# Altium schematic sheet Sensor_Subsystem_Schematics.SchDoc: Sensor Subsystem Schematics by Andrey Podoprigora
size A4; SheetNumber: 1; SheetTotal: 1
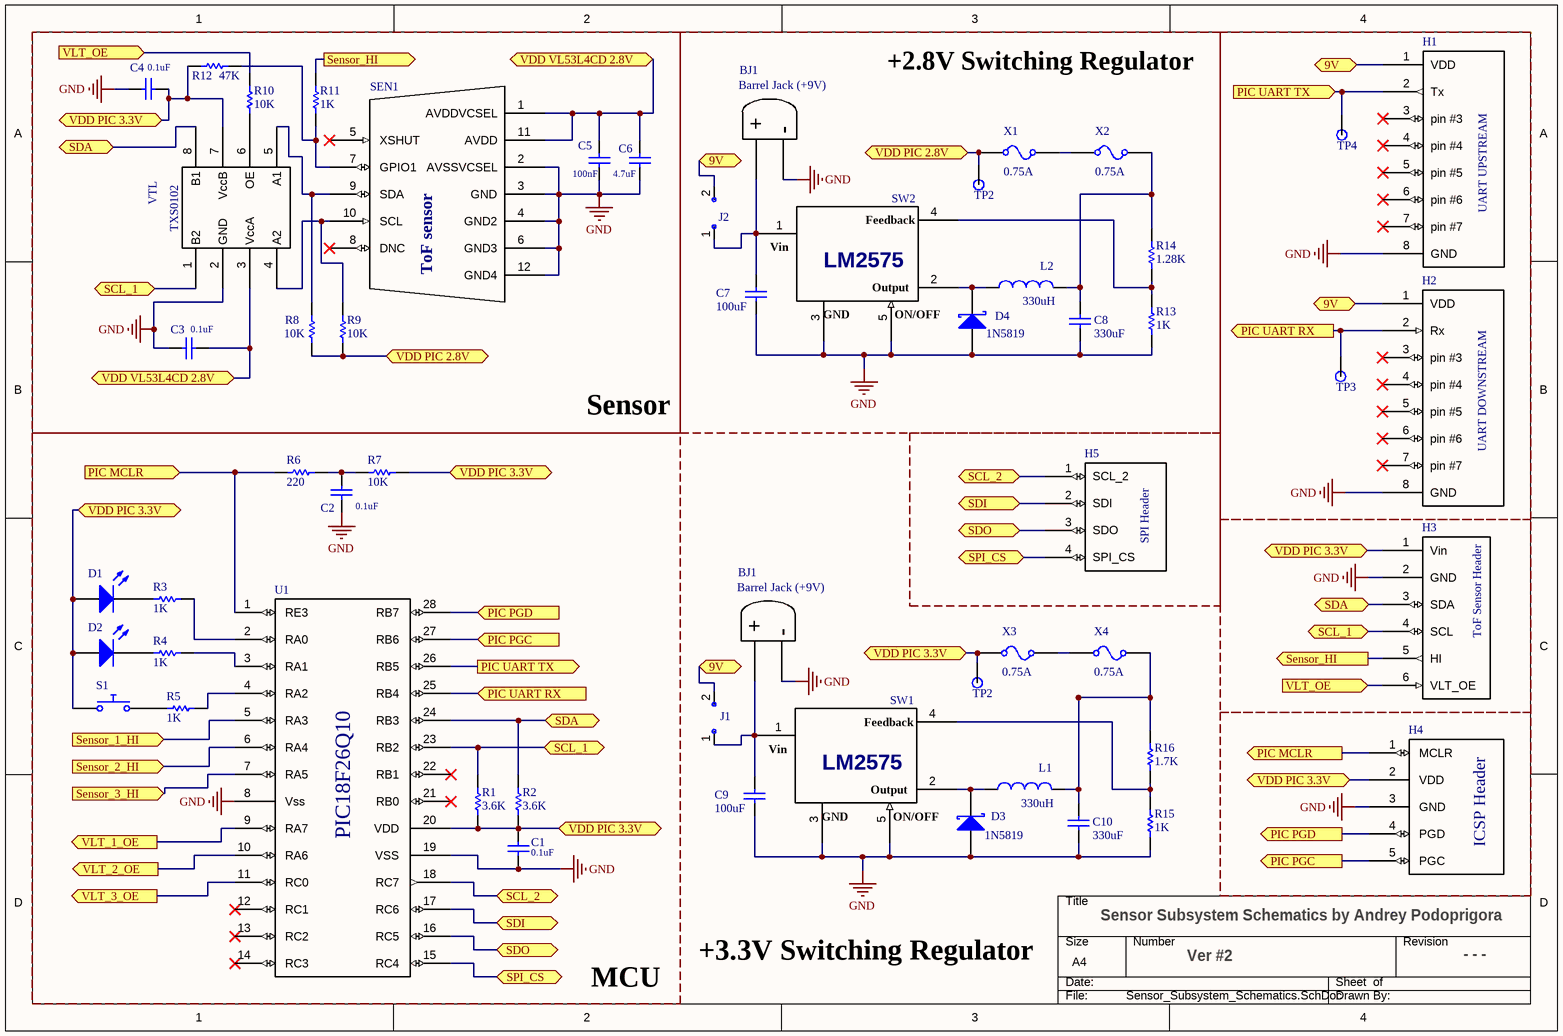
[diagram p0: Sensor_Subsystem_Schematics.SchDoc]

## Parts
(Parts that share a designator on the sheet are numbered #1, #2 ... from top to bottom, then left to right.)
BJ1#1  AP_Barrel_Jack_9v  (value not drawn)
BJ1#2  AP_Barrel_Jack_9v  (value not drawn)
C1  value 0.1uF  (hidden comment: Capacitor)
C2  value 0.1uF  (hidden comment: Capacitor)
C3  value 0.1uF  (hidden comment: Capacitor)
C4  value 0.1uF  (hidden comment: Capacitor)
C5  value 100nF  (hidden comment: Capacitor)
C6  value 4.7uF  (hidden comment: Capacitor)
C7  value 100uF  (hidden comment: Capacitor)
C8  value 330uF  (hidden comment: Capacitor)
C9  value 100uF  (hidden comment: Capacitor)
C10  value 330uF  (hidden comment: Capacitor)
D1  Light-Emitting Diode  (value not drawn)
D2  Light-Emitting Diode  (value not drawn)
D3  1N5819
D4  1N5819
H1  AP_UART_US  (value not drawn)
H2  AP_UART_DS  (value not drawn)
H3  AP_ToF_Header  (value not drawn)
H4  AP_ICSP_Header  (value not drawn)
H5  AP_SPI_Header  (value not drawn)
J1  AP_Jumper  (value not drawn)
J2  AP_Jumper  (value not drawn)
L1  value 330uH  (hidden comment: Inductor)
L2  value 330uH  (hidden comment: Inductor)
R1  value 3.6K  (hidden comment: Resistor)
R2  value 3.6K  (hidden comment: Resistor)
R3  value 1K  (hidden comment: Resistor)
R4  value 1K  (hidden comment: Resistor)
R5  value 1K  (hidden comment: Resistor)
R6  value 220  (hidden comment: Resistor)
R7  value 10K  (hidden comment: Resistor)
R8  value 10K  (hidden comment: Resistor)
R9  value 10K  (hidden comment: Resistor)
R10  value 10K  (hidden comment: Resistor)
R11  value 1K  (hidden comment: Resistor)
R12  value 47K  (hidden comment: Resistor)
R13  value 1K  (hidden comment: Resistor)
R14  value 1.28K  (hidden comment: Resistor)
R15  value 1K  (hidden comment: Resistor)
R16  value 1.7K  (hidden comment: Resistor)
S1  Push Button Normally Opened  (value not drawn)
SEN1  AP_VL53L4CD  (value not drawn)
SW1  AP_LM2575  (value not drawn)
SW2  AP_LM2575  (value not drawn)
TP2#1  AP_TP  (value not drawn)
TP2#2  AP_TP  (value not drawn)
TP3  AP_TP  (value not drawn)
TP4  AP_TP  (value not drawn)
U1  AP_PIC18F26Q10  (value not drawn)
VTL  AP_TXS0102  (value not drawn)
X1  CURRENT: 0.75A  (hidden comment: Fuse)
X2  CURRENT: 0.75A  (hidden comment: Fuse)
X3  CURRENT: 0.75A  (hidden comment: Fuse)
X4  CURRENT: 0.75A  (hidden comment: Fuse)

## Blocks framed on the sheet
Sensor: C3-C6 R8-R12 SEN1 VTL
+2.8V Switching Regulator: BJ1#1 C7 C8 D4 J2 L2 R13 R14 SW2 TP2#1 X1 X2
MCU: C1 C2 D1 D2 R1-R7 S1 U1

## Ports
9V (bidir, see Sensor_Subsystem_Schematics[1C], Sensor_Subsystem_Schematics[1D], Sensor_Subsystem_Schematics[3B]), 9V (bidir, see Sensor_Subsystem_Schematics[1C], Sensor_Subsystem_Schematics[1D], Sensor_Subsystem_Schematics[3D]), 9V (bidir, see Sensor_Subsystem_Schematics[1C], Sensor_Subsystem_Schematics[3B], Sensor_Subsystem_Schematics[3D]), 9V (bidir, see Sensor_Subsystem_Schematics[1D], Sensor_Subsystem_Schematics[3B], Sensor_Subsystem_Schematics[3D]), PIC MCLR (in, see Sensor_Subsystem_Schematics[1B]), PIC MCLR (out, see Sensor_Subsystem_Schematics[4C]), PIC PGC (in, see Sensor_Subsystem_Schematics[1A]), PIC PGC (out, see Sensor_Subsystem_Schematics[3B]), PIC PGD (in, see Sensor_Subsystem_Schematics[1A]), PIC PGD (out, see Sensor_Subsystem_Schematics[3B]), PIC UART RX (in, see Sensor_Subsystem_Schematics[1C]), PIC UART RX (out, see Sensor_Subsystem_Schematics[3B]), PIC UART TX (in, see Sensor_Subsystem_Schematics[3B]), PIC UART TX (out, see Sensor_Subsystem_Schematics[1D]), SCL_1 (bidir, see Sensor_Subsystem_Schematics[1B], Sensor_Subsystem_Schematics[3B]), SCL_1 (bidir, see Sensor_Subsystem_Schematics[1B], Sensor_Subsystem_Schematics[4C]), SCL_1 (bidir, see Sensor_Subsystem_Schematics[3B], Sensor_Subsystem_Schematics[4C]), SCL_2 (bidir, see Sensor_Subsystem_Schematics[2C]), SCL_2 (bidir, see Sensor_Subsystem_Schematics[3A]), SDA (bidir, see Sensor_Subsystem_Schematics[1B], Sensor_Subsystem_Schematics[3B]), SDA (bidir, see Sensor_Subsystem_Schematics[1B], Sensor_Subsystem_Schematics[4D]), SDA (bidir, see Sensor_Subsystem_Schematics[3B], Sensor_Subsystem_Schematics[4D]), SDI (bidir, see Sensor_Subsystem_Schematics[2C]), SDI (bidir, see Sensor_Subsystem_Schematics[3A]), SDO (bidir, see Sensor_Subsystem_Schematics[2B]), SDO (bidir, see Sensor_Subsystem_Schematics[3A]), Sensor_1_HI (in), Sensor_2_HI (in), Sensor_3_HI (in), Sensor_HI (out, see Sensor_Subsystem_Schematics[1B]), Sensor_HI (out, see Sensor_Subsystem_Schematics[4D]), SPI_CS (bidir, see Sensor_Subsystem_Schematics[2B]), SPI_CS (bidir, see Sensor_Subsystem_Schematics[3A]), VDD PIC 2.8V (bidir, see Sensor_Subsystem_Schematics[2D]), VDD PIC 2.8V (bidir, see Sensor_Subsystem_Schematics[4C]), VDD PIC 3.3V (bidir, see Sensor_Subsystem_Schematics[1A], Sensor_Subsystem_Schematics[1B], Sensor_Subsystem_Schematics[2B], Sensor_Subsystem_Schematics[3A], Sensor_Subsystem_Schematics[3C], Sensor_Subsystem_Schematics[4C]), VDD PIC 3.3V (bidir, see Sensor_Subsystem_Schematics[1A], Sensor_Subsystem_Schematics[1B], Sensor_Subsystem_Schematics[2B], Sensor_Subsystem_Schematics[3A], Sensor_Subsystem_Schematics[3C], Sensor_Subsystem_Schematics[4D]), VDD PIC 3.3V (bidir, see Sensor_Subsystem_Schematics[1A], Sensor_Subsystem_Schematics[1B], Sensor_Subsystem_Schematics[2B], Sensor_Subsystem_Schematics[3A], Sensor_Subsystem_Schematics[4C], Sensor_Subsystem_Schematics[4D]), VDD PIC 3.3V (bidir, see Sensor_Subsystem_Schematics[1A], Sensor_Subsystem_Schematics[1B], Sensor_Subsystem_Schematics[2B], Sensor_Subsystem_Schematics[3C], Sensor_Subsystem_Schematics[4C], Sensor_Subsystem_Schematics[4D]), VDD PIC 3.3V (bidir, see Sensor_Subsystem_Schematics[1A], Sensor_Subsystem_Schematics[1B], Sensor_Subsystem_Schematics[3A], Sensor_Subsystem_Schematics[3C], Sensor_Subsystem_Schematics[4C], Sensor_Subsystem_Schematics[4D]), VDD PIC 3.3V (bidir, see Sensor_Subsystem_Schematics[1A], Sensor_Subsystem_Schematics[2B], Sensor_Subsystem_Schematics[3A], Sensor_Subsystem_Schematics[3C], Sensor_Subsystem_Schematics[4C], Sensor_Subsystem_Schematics[4D]), VDD PIC 3.3V (bidir, see Sensor_Subsystem_Schematics[1B], Sensor_Subsystem_Schematics[2B], Sensor_Subsystem_Schematics[3A], Sensor_Subsystem_Schematics[3C], Sensor_Subsystem_Schematics[4C], Sensor_Subsystem_Schematics[4D]), VDD VL53L4CD 2.8V (bidir, see Sensor_Subsystem_Schematics[3D]), VDD VL53L4CD 2.8V (bidir, see Sensor_Subsystem_Schematics[4C]), VLT_1_OE (out), VLT_2_OE (out), VLT_3_OE (out), VLT_OE (in, see Sensor_Subsystem_Schematics[1B]), VLT_OE (in, see Sensor_Subsystem_Schematics[4D])

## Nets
GND: BJ1#1.1(-) BJ1#2.1(-) C1.1 C2.1 C3.1 C4.1 C5.1 C6.1 C7.1 C8.1 C9.1 C10.1 D3.1(A) D4.1(A) H1.8(GND) H2.8(GND) H3.2(GND) H4.3(GND) R13.1 R15.1 SEN1.2(AVSSVCSEL) SEN1.3(GND) SEN1.4(GND2) SEN1.6(GND3) SEN1.12(GND4) SW1.3(GND) SW1.5(ON/OFF) SW2.3(GND) SW2.5(ON/OFF) U1.8(Vss) U1.19(VSS) VTL.2(GND)
9V: H1.1(VDD) H2.1(VDD) J1.2 J2.2 ; port 9V
PIC MCLR: H4.1(MCLR) R6.1 U1.1(RE3) ; port PIC MCLR
PIC PGC: H4.5(PGC) U1.27(RB6) ; port PIC PGC
PIC PGD: H4.4(PGD) U1.28(RB7) ; port PIC PGD
PIC UART RX: H2.2(Rx) TP3.31 U1.25(RB4) ; port PIC UART RX
PIC UART TX: H1.2(Tx) TP4.31 U1.26(RB5) ; port PIC UART TX
SCL_1: H3.4(SCL) R1.2 U1.23(RB2) VTL.1(B2) ; port SCL_1
SCL_2: H5.1(SCL_2) U1.18(RC7) ; port SCL_2
SDA: H3.3(SDA) R2.2 U1.24(RB3) VTL.8(B1) ; port SDA
SDI: H5.2(SDI) U1.17(RC6) ; port SDI
SDO: H5.3(SDO) U1.16(RC5) ; port SDO
Sensor_1_HI: U1.5(RA3) ; port Sensor_1_HI
Sensor_2_HI: U1.6(RA4) ; port Sensor_2_HI
Sensor_3_HI: U1.7(RA5) ; port Sensor_3_HI
Sensor_HI: H3.5(HI) R11.2 ; port Sensor_HI
SPI_CS: H5.4(SPI_CS) U1.15(RC4) ; port SPI_CS
VDD PIC 2.8V: R8.1 R9.1 TP2#1.31 X1.1 ; port VDD PIC 2.8V
VDD PIC 3.3V: C1.2 C4.2 D1.1(A) D2.1(A) H3.1(Vin) H4.2(VDD) R1.1 R2.1 R7.2 R12.1 S1.1 TP2#2.31 U1.20(VDD) VTL.7(VccB) X3.1 ; port VDD PIC 3.3V
VDD VL53L4CD 2.8V: C3.2 C5.2 C6.2 SEN1.1(AVDDVCSEL) SEN1.11(AVDD) VTL.3(VccA) ; port VDD VL53L4CD 2.8V
VLT_1_OE: U1.9(RA7) ; port VLT_1_OE
VLT_2_OE: U1.10(RA6) ; port VLT_2_OE
VLT_3_OE: U1.11(RC0) ; port VLT_3_OE
VLT_OE: H3.6(VLT_OE) R10.2 ; port VLT_OE
NetBJ1#1_1: BJ1#1.1(+) C7.2 J2.1 SW2.1(Vin)
NetBJ1#2_1: BJ1#2.1(+) C9.2 J1.1 SW1.1(Vin)
NetC2_2: C2.2 R6.2 R7.1
NetC8_2: C8.2 L2.2 R14.2 X2.2
NetC10_2: C10.2 L1.2 R16.2 X4.2
NetD1_2: D1.2(K) R3.1
NetD2_2: D2.2(K) R4.1
NetD3_2: D3.2(K) L1.1 SW1.2(Output)
NetD4_2: D4.2(K) L2.1 SW2.2(Output)
NetR3_2: R3.2 U1.2(RA0)
NetR4_2: R4.2 U1.3(RA1)
NetR5_1: R5.1 S1.2
NetR5_2: R5.2 U1.4(RA2)
NetR8_2: R8.2 SEN1.9(SDA) VTL.5(A1)
NetR9_2: R9.2 SEN1.10(SCL) VTL.4(A2)
NetR10_1: R10.1 VTL.6(OE)
NetR11_1: R11.1 R12.2 SEN1.7(GPIO1)
NetR13_2: R13.2 R14.1 SW2.4(Feedback)
NetR15_2: R15.2 R16.1 SW1.4(Feedback)
NetX1_2: X1.2 X2.1
NetX3_2: X3.2 X4.1

Not connected (* = marked no-connect by the designer): H1 3(pin_#3)* 4(pin_#4)* 5(pin_#5)* 6(pin_#6)* 7(pin_#7)*; H2 3(pin_#3)* 4(pin_#4)* 5(pin_#5)* 6(pin_#6)* 7(pin_#7)*; SEN1 5(XSHUT)* 8(DNC)*; U1 12(RC1)* 13(RC2)* 14(RC3)* 21(RB0)* 22(RB1)*

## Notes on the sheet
- +3.3V Switching Regulator
- Ver #2
- - - -

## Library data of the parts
C1-C10 = Capacitor: SimulationGenericComponent: True
D1 D2 = LED: AF: 1; BV: 0; BV_MAX: 1e99; EG: 1.11; FC: 0.5; IBV: 0.001; IS: 1e-14; MJSW: 0.33; NTUN: 30; TNOM: 27; XTI: 3; SimulationGenericComponent: True
D3 D4 = Schottky Diode: AF: 1; BV: 0; BV_MAX: 1e99; EG: 1.11; FC: 0.5; IBV: 0.001; IS: 1e-14; MJSW: 0.33; NTUN: 30; TNOM: 27; XTI: 3; SimulationGenericComponent: True
H4 = AP_ICSP_Header: Header for the Microchip Snap
L1 L2 = Inductor: SimulationGenericComponent: True
R1-R16 = Resistor: TC1: 0; SimulationGenericComponent: True
S1 = Push Button NO: closed: 0; Rclosed: 1m; Ropen: 1Meg; SimulationGenericComponent: True
SEN1 = AP_VL53L4CD: Tof sensor type VL53L4CD
U1 = AP_PIC18F26Q10: PIC18F26Q10 represented as a library element
X1-X4 = Fuse: RESISTANCE: 1m; SimulationGenericComponent: True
